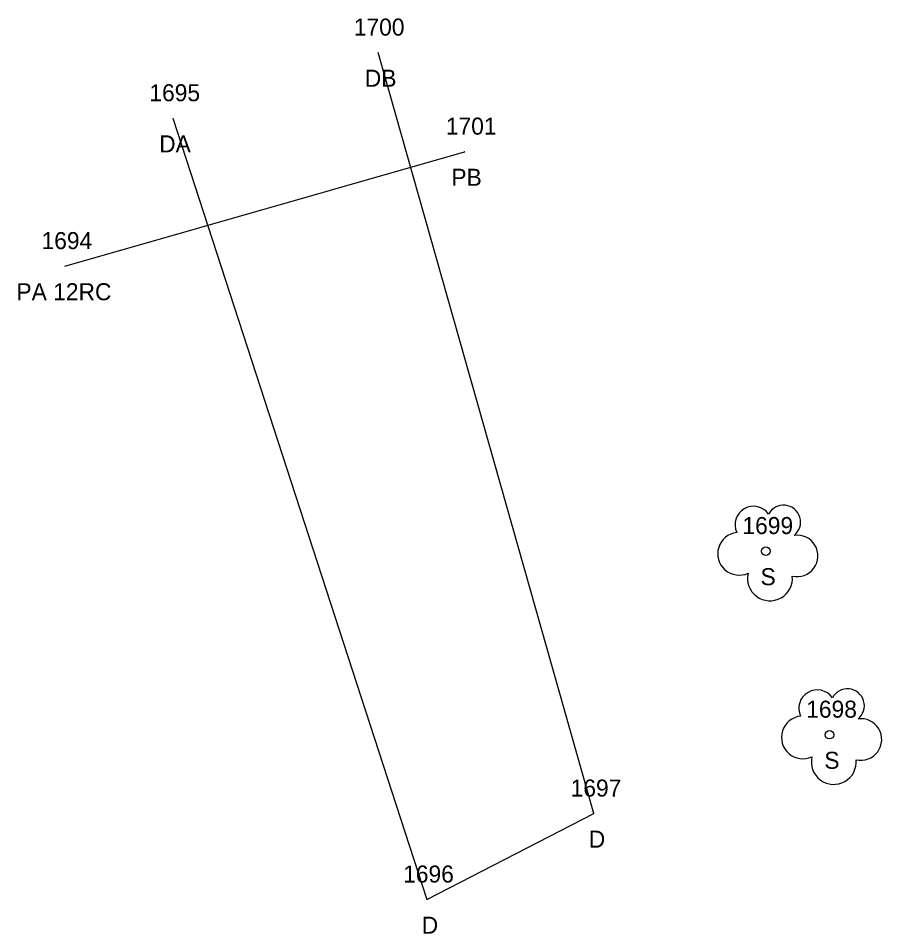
# Model space of a CAD drawing. Extents: x 1965822 to 1970313, y 1117097 to 1118160.
# Drawn here: x 1966297 to 1966347.6, y 1117280 to 1117333.7 of the extents above; entities that cross this region are included whole.
import ezdxf

# ---------------------------------------------------------------- set-up
doc = ezdxf.new("R2010")
doc.units = 0
for name, color, linetype in [('RD_EX_DR_Pipe', 7, 'Continuous'), ('RD_EX_DR_Pipe_txCode', 7, 'Continuous'), ('RD_EX_Driveway', 7, 'Continuous'), ('RD_EX_Driveway_txCode', 7, 'Continuous'), ('RD_EX_VEG', 7, 'Continuous'), ('RD_EX_VEG_txCode', 7, 'Continuous'), ('RD_SMD_Locator', 7, 'Continuous')]:
    doc.layers.add(name, color=color, linetype=linetype)

msp = doc.modelspace()

# ---------------------------------------------------------------- linework, layer by layer
at = {"layer": 'RD_EX_DR_Pipe'}
msp.add_line((1966299.711, 1117319.139), (1966323.166, 1117325.855), dxfattribs=at)
at = {"layer": 'RD_EX_Driveway'}
msp.add_lwpolyline([(1966306.038, 1117327.815), (1966320.953, 1117281.973), (1966330.755, 1117287.02), (1966318.088, 1117331.667)], dxfattribs=at)
at = {"layer": 'RD_EX_VEG'}
for centre in [(1966340.834, 1117302.42), (1966344.577, 1117291.647)]:
    msp.add_circle(centre, 0.25, dxfattribs=at)
for centre, radius, start, end in [((1966340.113, 1117303.967), 1.084, 34.9763, 204.756), ((1966341.879, 1117304.122), 0.995, 308.7626, 152.0467), ((1966339.27, 1117302.264), 1.257, 96.4518, 294.734), ((1966342.674, 1117302.14), 1.218, 256.5667, 98.1046), ((1966341.08, 1117300.823), 1.318, 166.8827, 5.7589), ((1966343.856, 1117293.194), 1.084, 34.9763, 204.756), ((1966345.622, 1117293.349), 0.995, 308.7626, 152.0467), ((1966343.013, 1117291.492), 1.257, 96.4518, 294.734), ((1966346.417, 1117291.368), 1.218, 256.5667, 98.1046), ((1966344.823, 1117290.051), 1.318, 166.8827, 5.7589)]:
    msp.add_arc(centre, radius, start, end, dxfattribs=at)
at = {"layer": 'RD_SMD_Locator'}
for centre in [(1966318.088, 1117331.667), (1966306.038, 1117327.815), (1966323.166, 1117325.855), (1966299.711, 1117319.139), (1966330.755, 1117287.02), (1966320.953, 1117281.973)]:
    msp.add_circle(centre, 0.001, dxfattribs=at)

# ---------------------------------------------------------------- texts
at = {"layer": 'RD_EX_DR_Pipe_txCode'}
for s, p in [('1701', (1966322.063, 1117326.855)), ('PB', (1966322.386, 1117323.855)), ('1694', (1966298.341, 1117320.139)), ('PA 12RC', (1966296.868, 1117317.139))]:
    msp.add_text(s, height=1, dxfattribs=at).set_placement(p)
at = {"layer": 'RD_EX_Driveway_txCode'}
for s, p in [('1700', (1966316.662, 1117332.667)), ('DB', (1966317.308, 1117329.667)), ('1695', (1966304.668, 1117328.815)), ('DA', (1966305.243, 1117325.815)), ('1697', (1966329.385, 1117288.02)), ('D', (1966330.448, 1117285.02)), ('1696', (1966319.559, 1117282.973)), ('D', (1966320.646, 1117279.973))]:
    msp.add_text(s, height=1, dxfattribs=at).set_placement(p)
at = {"layer": 'RD_EX_VEG_txCode'}
for s, p in [('1699', (1966339.464, 1117303.42)), ('S', (1966340.527, 1117300.42)), ('1698', (1966343.207, 1117292.647)), ('S', (1966344.27, 1117289.647))]:
    msp.add_text(s, height=1, dxfattribs=at).set_placement(p)

doc.saveas('drawing.dxf')
